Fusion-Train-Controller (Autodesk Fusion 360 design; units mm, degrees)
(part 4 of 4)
sketch "Button head" plane through (0, 0, 66) normal (0, 0, 1) x axis (1, 0, 0)
  circle C1 centre (30, -85) radius 4.75
extrude "Extrude2" add sketch "Button head" along normal blind 2.75
work_plane "WorkPlane1" AlongDistance 63 ExtraOffset 0
sketch "Rail M5 metal spacer 3mm (30, -1)" plane through (0, 0, 63) normal (0, 0, 1) x axis (1, 0, 0)
  circle C1 centre (30, -85) radius 5
extrude "Extrude1" new body sketch "Rail M5 metal spacer 3mm (30, -1)" along normal blind 3 bodies "HARDWARE Rail M5 metal spacer 3mm (30, -1)"
work_plane "WorkPlane2" AlongDistance 62.9 ExtraOffset 0
sketch "Washer clearance" plane through (0, 0, 62.9) normal (0, 0, 1) x axis (1, 0, 0)
  circle C1 centre (30, -85) radius 2.7
extrude "Extrude2" cut sketch "Washer clearance" along normal blind 3.2
work_plane "WorkPlane1" AlongDistance 50 ExtraOffset 0
sketch "Rail vertical M5x16 (30, 1)" plane through (0, 0, 50) normal (0, 0, 1) x axis (1, 0, 0)
  circle C1 centre (30, 85) radius 2.5
extrude "Extrude1" new body sketch "Rail vertical M5x16 (30, 1)" along normal blind 16 bodies "HARDWARE Rail vertical M5x16 (30, 1)"
work_plane "WorkPlane2" AlongDistance 66 ExtraOffset 0
sketch "Button head" plane through (0, 0, 66) normal (0, 0, 1) x axis (1, 0, 0)
  circle C1 centre (30, 85) radius 4.75
extrude "Extrude2" add sketch "Button head" along normal blind 2.75
work_plane "WorkPlane1" AlongDistance 63 ExtraOffset 0
sketch "Rail M5 metal spacer 3mm (30, 1)" plane through (0, 0, 63) normal (0, 0, 1) x axis (1, 0, 0)
  circle C1 centre (30, 85) radius 5
extrude "Extrude1" new body sketch "Rail M5 metal spacer 3mm (30, 1)" along normal blind 3 bodies "HARDWARE Rail M5 metal spacer 3mm (30, 1)"
work_plane "WorkPlane2" AlongDistance 62.9 ExtraOffset 0
sketch "Washer clearance" plane through (0, 0, 62.9) normal (0, 0, 1) x axis (1, 0, 0)
  circle C1 centre (30, 85) radius 2.7
extrude "Extrude2" cut sketch "Washer clearance" along normal blind 3.2
work_plane "WorkPlane1" AlongDistance -36.5 ExtraOffset 0
sketch "Follower pivot M3x80" plane through (-36.5, 0, 0) normal (1, 0, 0) x axis (0, 0, -1)
  circle C1 centre (-12, -35) radius 1.5
extrude "Extrude1" new body sketch "Follower pivot M3x80" along normal blind 80 bodies "HARDWARE Follower pivot M3x80"
work_plane "WorkPlane2" AlongDistance -38.15 ExtraOffset 0
sketch "Button head" plane through (-38.15, 0, 0) normal (1, 0, 0) x axis (0, 0, -1)
  circle C1 centre (-12, -35) radius 2.85
extrude "Extrude2" add sketch "Button head" along normal blind 1.65
work_plane "WorkPlane1" AlongDistance -36.5 ExtraOffset 0
sketch "Follower pivot M3 washer -36.5" plane through (-36.5, 0, 0) normal (1, 0, 0) x axis (0, 0, -1)
  circle C1 centre (-12, -35) radius 3.5
extrude "Extrude1" new body sketch "Follower pivot M3 washer -36.5" along normal blind 0.5 bodies "HARDWARE Follower pivot M3 washer -36.5"
work_plane "WorkPlane2" AlongDistance -36.6 ExtraOffset 0
sketch "Washer clearance" plane through (-36.6, 0, 0) normal (1, 0, 0) x axis (0, 0, -1)
  circle C1 centre (-12, -35) radius 1.7
extrude "Extrude2" cut sketch "Washer clearance" along normal blind 0.7
work_plane "WorkPlane1" AlongDistance 36 ExtraOffset 0
sketch "Follower pivot M3 washer 36" plane through (36, 0, 0) normal (1, 0, 0) x axis (0, 0, -1)
  circle C1 centre (-12, -35) radius 3.5
extrude "Extrude1" new body sketch "Follower pivot M3 washer 36" along normal blind 0.5 bodies "HARDWARE Follower pivot M3 washer 36"
work_plane "WorkPlane2" AlongDistance 35.9 ExtraOffset 0
sketch "Washer clearance" plane through (35.9, 0, 0) normal (1, 0, 0) x axis (0, 0, -1)
  circle C1 centre (-12, -35) radius 1.7
extrude "Extrude2" cut sketch "Washer clearance" along normal blind 0.7
work_plane "WorkPlane1" AlongDistance 36.5 ExtraOffset 0
sketch "Follower pivot M3 locknut" plane through (36.5, 0, 0) normal (1, 0, 0) x axis (0, 0, -1)
  line L1 (-14.75, -33.4123) -> (-12, -31.8246)
  line L2 (-14.75, -36.5877) -> (-14.75, -33.4123)
  line L3 (-12, -38.1754) -> (-14.75, -36.5877)
  line L4 (-9.25, -36.5877) -> (-12, -38.1754)
  line L5 (-9.25, -33.4123) -> (-9.25, -36.5877)
  line L6 (-12, -31.8246) -> (-9.25, -33.4123)
extrude "Extrude1" new body sketch "Follower pivot M3 locknut" along normal blind 4 bodies "HARDWARE Follower pivot M3 locknut"
work_plane "WorkPlane2" AlongDistance 36.4 ExtraOffset 0
sketch "Thread envelope" plane through (36.4, 0, 0) normal (1, 0, 0) x axis (0, 0, -1)
  circle C1 centre (-12, -35) radius 1.5
extrude "Extrude2" cut sketch "Thread envelope" along normal blind 4.2
work_plane "WorkPlane1" AlongDistance -36.5 ExtraOffset 0
sketch "Stop M3 washer -1" plane through (-36.5, 0, 0) normal (1, 0, 0) x axis (0, 0, -1)
  circle C1 centre (-79.6754, -33.9652) radius 3.5
extrude "Extrude1" new body sketch "Stop M3 washer -1" along normal blind 0.5 bodies "HARDWARE Stop M3 washer -1"
work_plane "WorkPlane2" AlongDistance -36.6 ExtraOffset 0
sketch "Washer clearance" plane through (-36.6, 0, 0) normal (1, 0, 0) x axis (0, 0, -1)
  circle C1 centre (-79.6754, -33.9652) radius 1.7
extrude "Extrude2" cut sketch "Washer clearance" along normal blind 0.7
work_plane "WorkPlane1" AlongDistance -36.5 ExtraOffset 0
sketch "Stop M3 washer 1" plane through (-36.5, 0, 0) normal (1, 0, 0) x axis (0, 0, -1)
  circle C1 centre (-79.6754, 33.9652) radius 3.5
extrude "Extrude1" new body sketch "Stop M3 washer 1" along normal blind 0.5 bodies "HARDWARE Stop M3 washer 1"
work_plane "WorkPlane2" AlongDistance -36.6 ExtraOffset 0
sketch "Washer clearance" plane through (-36.6, 0, 0) normal (1, 0, 0) x axis (0, 0, -1)
  circle C1 centre (-79.6754, 33.9652) radius 1.7
extrude "Extrude2" cut sketch "Washer clearance" along normal blind 0.7
work_plane "WorkPlane1" AlongDistance -24 ExtraOffset 0
sketch "Center M3 bolt in retained metal pivot sleeve" plane through (-24, 0, 0) normal (1, 0, 0) x axis (0, 0, -1)
  circle C1 centre (-12, -35) radius 2.5
extrude "Extrude1" new body sketch "Center M3 bolt in retained metal pivot sleeve" along normal blind 6 bodies "P25 Left pivot sleeve centering insert"
work_plane "WorkPlane2" AlongDistance -24.1 ExtraOffset 0
sketch "M3 running clearance" plane through (-24.1, 0, 0) normal (1, 0, 0) x axis (0, 0, -1)
  circle C1 centre (-12, -35) radius 1.7
extrude "Extrude2" cut sketch "M3 running clearance" along normal blind 6.2
work_plane "WorkPlane1" AlongDistance 18 ExtraOffset 0
sketch "Center M3 bolt in retained metal pivot sleeve" plane through (18, 0, 0) normal (1, 0, 0) x axis (0, 0, -1)
  circle C1 centre (-12, -35) radius 2.5
extrude "Extrude1" new body sketch "Center M3 bolt in retained metal pivot sleeve" along normal blind 6 bodies "P26 Right pivot sleeve centering insert"
work_plane "WorkPlane2" AlongDistance 17.9 ExtraOffset 0
sketch "M3 running clearance" plane through (17.9, 0, 0) normal (1, 0, 0) x axis (0, 0, -1)
  circle C1 centre (-12, -35) radius 1.7
extrude "Extrude2" cut sketch "M3 running clearance" along normal blind 6.2
ground "Pin70"
ground "Pin71"
ground "Pin72"
ground "Pin73"
ground "Pin74"
ground "Pin75"
ground "Pin76"
ground "Pin77"
ground "Pin78"
ground "Pin79"
ground "Pin80"
ground "Pin81"
ground "Pin83"
ground "Pin86"
ground "Pin88"
ground "Pin89"
work_plane "WorkPlane56" AlongDistance -17.5 ExtraOffset 0
sketch "Recess M3 locknut to keep bolt inside stop" plane through (-17.5, 0, 0) normal (1, 0, 0) x axis (0, 0, -1)
  line L1 (-82.5754, -32.2908) -> (-79.6754, -30.6165)
  line L2 (-82.5754, -35.6395) -> (-82.5754, -32.2908)
  line L3 (-79.6754, -37.3138) -> (-82.5754, -35.6395)
  line L4 (-76.7754, -35.6395) -> (-79.6754, -37.3138)
  line L5 (-76.7754, -32.2908) -> (-76.7754, -35.6395)
  line L6 (-79.6754, -30.6165) -> (-76.7754, -32.2908)
extrude "Extrude56" cut sketch "Recess M3 locknut to keep bolt inside stop" along normal blind 4.01
work_plane "WorkPlane1" AlongDistance -36.5 ExtraOffset 0
sketch "Stop steel core M3x25 -1" plane through (-36.5, 0, 0) normal (1, 0, 0) x axis (0, 0, -1)
  circle C1 centre (-79.6754, -33.9652) radius 1.5
extrude "Extrude1" new body sketch "Stop steel core M3x25 -1" along normal blind 25 bodies "HARDWARE Stop steel core M3x25 -1"
work_plane "WorkPlane2" AlongDistance -38.15 ExtraOffset 0
sketch "Button head" plane through (-38.15, 0, 0) normal (1, 0, 0) x axis (0, 0, -1)
  circle C1 centre (-79.6754, -33.9652) radius 2.85
extrude "Extrude2" add sketch "Button head" along normal blind 1.65
work_plane "WorkPlane1" AlongDistance -17.5 ExtraOffset 0
sketch "Stop retained M3 locknut -1" plane through (-17.5, 0, 0) normal (1, 0, 0) x axis (0, 0, -1)
  line L1 (-82.4254, -32.3774) -> (-79.6754, -30.7897)
  line L2 (-82.4254, -35.5529) -> (-82.4254, -32.3774)
  line L3 (-79.6754, -37.1406) -> (-82.4254, -35.5529)
  line L4 (-76.9254, -35.5529) -> (-79.6754, -37.1406)
  line L5 (-76.9254, -32.3774) -> (-76.9254, -35.5529)
  line L6 (-79.6754, -30.7897) -> (-76.9254, -32.3774)
extrude "Extrude1" new body sketch "Stop retained M3 locknut -1" along normal blind 4 bodies "HARDWARE Stop retained M3 locknut -1"
work_plane "WorkPlane2" AlongDistance -17.6 ExtraOffset 0
sketch "Thread envelope" plane through (-17.6, 0, 0) normal (1, 0, 0) x axis (0, 0, -1)
  circle C1 centre (-79.6754, -33.9652) radius 1.5
extrude "Extrude2" cut sketch "Thread envelope" along normal blind 4.2
work_plane "WorkPlane57" AlongDistance -17.5 ExtraOffset 0
sketch "Recess M3 locknut to keep bolt inside stop (1)" plane through (-17.5, 0, 0) normal (1, 0, 0) x axis (0, 0, -1)
  line L1 (-82.5754, 35.6395) -> (-79.6754, 37.3138)
  line L2 (-82.5754, 32.2908) -> (-82.5754, 35.6395)
  line L3 (-79.6754, 30.6165) -> (-82.5754, 32.2908)
  line L4 (-76.7754, 32.2908) -> (-79.6754, 30.6165)
  line L5 (-76.7754, 35.6395) -> (-76.7754, 32.2908)
  line L6 (-79.6754, 37.3138) -> (-76.7754, 35.6395)
extrude "Extrude57" cut sketch "Recess M3 locknut to keep bolt inside stop (1)" along normal blind 4.01
work_plane "WorkPlane1" AlongDistance -36.5 ExtraOffset 0
sketch "Stop steel core M3x25 1" plane through (-36.5, 0, 0) normal (1, 0, 0) x axis (0, 0, -1)
  circle C1 centre (-79.6754, 33.9652) radius 1.5
extrude "Extrude1" new body sketch "Stop steel core M3x25 1" along normal blind 25 bodies "HARDWARE Stop steel core M3x25 1"
work_plane "WorkPlane2" AlongDistance -38.15 ExtraOffset 0
sketch "Button head" plane through (-38.15, 0, 0) normal (1, 0, 0) x axis (0, 0, -1)
  circle C1 centre (-79.6754, 33.9652) radius 2.85
extrude "Extrude2" add sketch "Button head" along normal blind 1.65
work_plane "WorkPlane1" AlongDistance -17.5 ExtraOffset 0
sketch "Stop retained M3 locknut 1" plane through (-17.5, 0, 0) normal (1, 0, 0) x axis (0, 0, -1)
  line L1 (-82.4254, 35.5529) -> (-79.6754, 37.1406)
  line L2 (-82.4254, 32.3774) -> (-82.4254, 35.5529)
  line L3 (-79.6754, 30.7897) -> (-82.4254, 32.3774)
  line L4 (-76.9254, 32.3774) -> (-79.6754, 30.7897)
  line L5 (-76.9254, 35.5529) -> (-76.9254, 32.3774)
  line L6 (-79.6754, 37.1406) -> (-76.9254, 35.5529)
extrude "Extrude1" new body sketch "Stop retained M3 locknut 1" along normal blind 4 bodies "HARDWARE Stop retained M3 locknut 1"
work_plane "WorkPlane2" AlongDistance -17.6 ExtraOffset 0
sketch "Thread envelope" plane through (-17.6, 0, 0) normal (1, 0, 0) x axis (0, 0, -1)
  circle C1 centre (-79.6754, 33.9652) radius 1.5
extrude "Extrude2" cut sketch "Thread envelope" along normal blind 4.2
ground "Pin90"
ground "Pin91"
ground "Pin92"
ground "Pin93"
work_plane "WorkPlane12" AlongDistance 0 ExtraOffset 0
sketch "Support-free flange ramp profile" plane through (0, 0, 0) normal (0, 1, 0) x axis (1, 0, 0)
  line L1 (48, -76) -> (44, -72)
  line L2 (48, -72) -> (48, -76)
  line L3 (44, -72) -> (48, -72)
  line L4 (51, -65) -> (40, -65)
revolve "Revolve1" sketch "Support-free flange ramp profile" AlongAngle 360
work_plane "WorkPlane13" AlongDistance 40.4 ExtraOffset 0
sketch "Preserve clamp flexure through flange ramp" plane through (40.4, 0, 0) normal (1, 0, 0) x axis (0, 0, -1)
  line L1 (-65, 0.2) -> (-65, -0.2)
  line L2 (-79, 0.2) -> (-65, 0.2)
  line L3 (-79, -0.2) -> (-79, 0.2)
  line L4 (-65, -0.2) -> (-79, -0.2)
extrude "Extrude12" cut sketch "Preserve clamp flexure through flange ramp" along normal blind 10.2
work_plane "WorkPlane14" AlongDistance -7.2 ExtraOffset 0
sketch "Preserve insert pocket through flange ramp" plane through (0, -7.2, 0) normal (0, 1, 0) x axis (1, 0, 0)
  circle C1 centre (45.5, -73) radius 2
extrude "Extrude13" cut sketch "Preserve insert pocket through flange ramp" along normal blind 7.1
work_plane "WorkPlane15" AlongDistance 0.1 ExtraOffset 0
sketch "Preserve clamp screw through flange ramp" plane through (0, 0.1, 0) normal (0, 1, 0) x axis (1, 0, 0)
  circle C1 centre (45.5, -73) radius 1.7
extrude "Extrude14" cut sketch "Preserve clamp screw through flange ramp" along normal blind 9
work_plane "WorkPlane6" AlongDistance -7.2 ExtraOffset 0
sketch "Upright socket roof 45 degrees" plane through (0, -7.2, 0) normal (0, 1, 0) x axis (1, 0, 0)
  line L1 (-7.2, -196) -> (0, -196)
  line L2 (0, -203.2) -> (-7.2, -196)
  line L3 (0, -196) -> (0, -203.2)
extrude "Extrude5" cut sketch "Upright socket roof 45 degrees" along normal blind 14.4
work_plane "WorkPlane8" AlongDistance -7.2 ExtraOffset 0
sketch "Upright socket roof 45 degrees" plane through (0, -7.2, 0) normal (0, 1, 0) x axis (1, 0, 0)
  line L1 (7.2, -196) -> (0, -196)
  line L2 (0, -203.2) -> (7.2, -196)
  line L3 (0, -196) -> (0, -203.2)
extrude "Extrude7" cut sketch "Upright socket roof 45 degrees" along normal blind 14.4
work_plane "WorkPlane16" AlongDistance 9 ExtraOffset 0
sketch "Flat clearance around coupler washer on ramp" plane through (0, 9, 0) normal (0, 1, 0) x axis (1, 0, 0)
  circle C1 centre (45.5, -73) radius 3.6
extrude "Extrude15" cut sketch "Flat clearance around coupler washer on ramp" along normal blind 4
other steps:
create_component "CreateComponent1"
create_component "CreateComponent2"
create_component "CreateComponent3"
create_component "CreateComponent4"
create_component "CreateComponent5"
create_component "CreateComponent6"
create_component "CreateComponent7"
create_component "CreateComponent8"
create_component "CreateComponent9"
create_component "CreateComponent10"
create_component "CreateComponent11"
create_component "CreateComponent12"
create_component "CreateComponent13"
create_component "CreateComponent14"
create_component "CreateComponent15"
create_component "CreateComponent16"
create_component "CreateComponent17"
create_component "CreateComponent19"
create_component "CreateComponent20"
create_component "CreateComponent21"
create_component "CreateComponent22"
create_component "CreateComponent23"
create_component "CreateComponent24"
create_component "CreateComponent25"
create_component "CreateComponent26"
create_component "CreateComponent27"
create_component "CreateComponent28"
create_component "CreateComponent29"
create_component "CreateComponent30"
create_component "CreateComponent31"
create_component "CreateComponent32"
create_component "CreateComponent33"
create_component "CreateComponent34"
create_component "CreateComponent35"
create_component "CreateComponent36"
create_component "CreateComponent37"
create_component "CreateComponent48"
create_component "CreateComponent49"
create_component "CreateComponent61"
create_component "CreateComponent66"
create_component "CreateComponent67"
create_component "CreateComponent68"
create_component "CreateComponent69"
create_component "CreateComponent70"
create_component "CreateComponent71"
create_component "CreateComponent72"
create_component "CreateComponent73"
create_component "CreateComponent74"
create_component "CreateComponent75"
create_component "CreateComponent76"
create_component "CreateComponent77"
create_component "CreateComponent89"
create_component "CreateComponent90"
create_component "CreateComponent91"
create_component "CreateComponent92"
create_component "CreateComponent93"
create_component "CreateComponent94"
create_component "CreateComponent95"
create_component "CreateComponent96"
create_component "CreateComponent97"
create_component "CreateComponent98"
create_component "CreateComponent99"
create_component "CreateComponent102"
create_component "CreateComponent111"
create_component "CreateComponent112"
create_component "CreateComponent113"
create_component "CreateComponent114"
create_component "CreateComponent115"
create_component "CreateComponent116"
create_component "CreateComponent117"
create_component "CreateComponent118"
create_component "CreateComponent119"
create_component "CreateComponent120"
create_component "CreateComponent121"
create_component "CreateComponent122"
create_component "CreateComponent123"
create_component "CreateComponent124"
create_component "CreateComponent125"
create_component "CreateComponent126"
create_component "CreateComponent127"
create_component "CreateComponent129"
create_component "CreateComponent132"
create_component "CreateComponent134"
create_component "CreateComponent135"
create_component "CreateComponent136"
create_component "CreateComponent137"
create_component "CreateComponent138"
create_component "CreateComponent139"
named bodies: "P01 Left rail sideplate", "P02 Right rail sideplate", "P03 Left flanged journal bush", "P04 Right flanged journal bush", "P05 Printed main shaft - horizontal print", "P06 Shaft retaining cap", "P07 Integral lever rotor and cam carrier", "P08 Cam 7 gates - stable endpoints", "P08 Cam 5 gates - stable endpoints", "P08 Cam 3 gates - stable endpoints", "P09 Grip insert half", "P10 Grip screw half", "P11 Forked roller follower", "P12 Replaceable plain roller", "P13 Spring reaction crossblock", "P14 Captive spring cup", "HARDWARE H01 Pivot sleeve 8OD 5.2ID x48", "HARDWARE H02 Roller spacer 4OD 3.2ID x10", "REFERENCE spring 8OD 5ID - 17 mm installed", "P16 Sliding replaceable RK097 mount", "P17 Shaft side floating coupling hub", "P18 Floating cross-slot coupling disc", "P19 RK097 clamp insert half", "P20 RK097 clamp screw half", "REFERENCE RK097 ASSUMED envelope - verify actual part", "P21 Follower left axial spacer", "P22 Follower right axial spacer", "HARDWARE Guide tube 4OD 3.2ID x6 at 5", "HARDWARE Guide tube 4OD 3.2ID x6 at 19", "HARDWARE Main shaft cap M3x8", "HARDWARE Cam fastener M3x10 -45", "HARDWARE Cam fastener M3x10 0", "HARDWARE Cam fastener M3x10 45", "HARDWARE Grip fastener M3x25 180", "HARDWARE Grip fastener M3x25 190", "HARDWARE Roller axle M3x20", "HARDWARE Roller axle M3 nut", "HARDWARE Retained preload M4 nut", "HARDWARE Coupler clamp M3x16 (45.5, 73)", "HARDWARE Coupler clamp washer (45.5, 73)", "HARDWARE Coupler clamp M3x16 (67, 58)", "HARDWARE Coupler clamp washer (67, 58)", "HARDWARE Coupler clamp M3x16 (67, 72)", "HARDWARE Coupler clamp washer (67, 72)", "HARDWARE RK097 carriage M3x12 -1", "HARDWARE RK097 carriage washer -1", "HARDWARE RK097 carriage M3x12 1", "HARDWARE RK097 carriage washer 1", "HARDWARE RK097 assumed M7 washer", "HARDWARE RK097 assumed M7 nut", "P23 Left rotor thrust spacer", "P24 Right rotor thrust spacer", "P15 Preload limit collar 2 mm", "HARDWARE Cup guide M3x35 5", "HARDWARE Cup guide washer 5", "HARDWARE Cup guide M3 nut 5", "HARDWARE Cup guide M3x35 19", "HARDWARE Cup guide washer 19", "HARDWARE Cup guide M3 nut 19", "HARDWARE Spring block M3x20 (-62, -1)"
